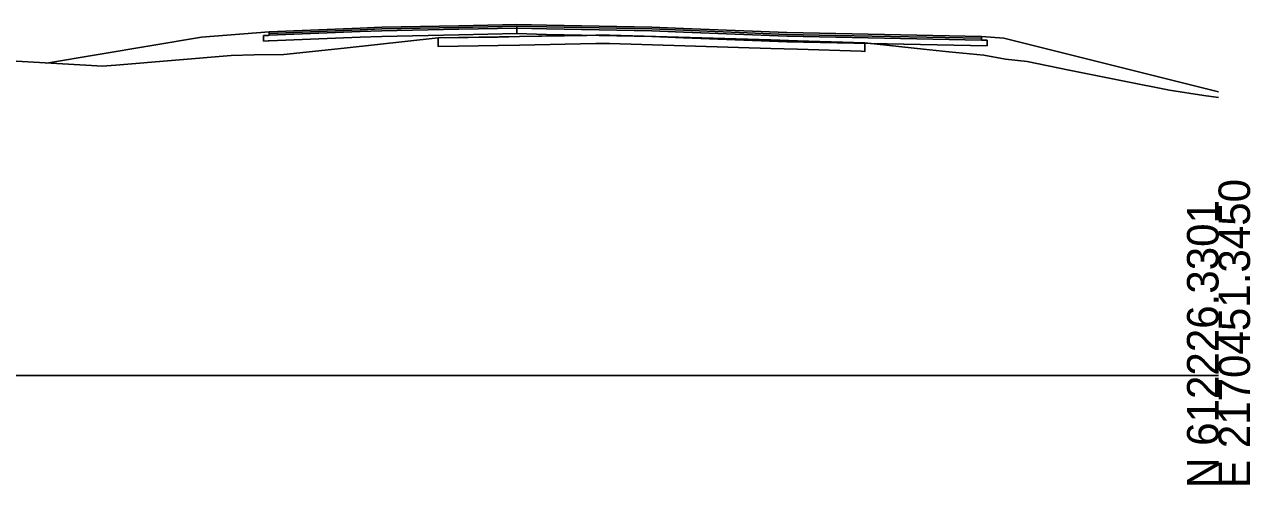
# Model space of a CAD drawing. Extents: x -26 to 1303, y -3010 to 12038.
# Drawn here: x 193.9 to 302.8, y 10990.3 to 11031.2 of the extents above; entities that cross this region are included whole.
import ezdxf

# ---------------------------------------------------------------- set-up
doc = ezdxf.new("R2010")
doc.units = 0
for name, color, linetype in [('RD_GPK_XS_Cell', 7, 'Continuous'), ('RD_XS_Base', 7, 'Continuous'), ('RD_XS_ExGround', 7, 'Continuous'), ('RD_XS_ExPaveRet', 7, 'Continuous'), ('RD_XS_Greenside', 7, 'Continuous'), ('RD_XS_Pave', 7, 'Continuous'), ('RD_XS_PaveOvlay_CP', 7, 'Continuous'), ('RD_XS_TieSlope', 7, 'Continuous')]:
    doc.layers.add(name, color=color, linetype=linetype)

msp = doc.modelspace()

# ---------------------------------------------------------------- linework, layer by layer
at = {"layer": 'RD_GPK_XS_Cell'}
msp.add_line((150, 11000), (300, 11000), dxfattribs=at)
at = {"layer": 'RD_XS_Base'}
for p, q in [((215.13, 11030.25), (215.54, 11030.26)), ((215.13, 11030.16), (215.13, 11030.25)), ((215.13, 11029.75), (215.13, 11030.16)), ((215.54, 11030.26), (215.63, 11030.27)), ((215.63, 11030.27), (223.73, 11030.59)), ((223.73, 11030.59), (225.63, 11030.67)), ((225.63, 11030.17), (223.73, 11030.09)), ((225.63, 11030.67), (232.5, 11030.8)), ((232.5, 11030.3), (225.63, 11030.17)), ((232.5, 11030.8), (237.63, 11030.91)), ((237.63, 11030.41), (232.5, 11030.3)), ((237.63, 11031.03), (237.63, 11031.07)), ((237.63, 11031.07), (237.63, 11030.92)), ((237.63, 11030.91), (237.63, 11031.03)), ((237.63, 11030.92), (237.63, 11030.41)), ((237.63, 11030.91), (237.63, 11030.91)), ((240.29, 11030.85), (237.63, 11030.91)), ((237.63, 11030.91), (237.63, 11030.91)), ((237.63, 11030.91), (237.63, 11030.8)), ((237.63, 11030.8), (237.63, 11030.41)), ((237.63, 11030.41), (240.29, 11030.35)), ((249.63, 11030.67), (240.29, 11030.85)), ((240.29, 11030.35), (249.63, 11030.17)), ((252.46, 11030.55), (249.63, 11030.67)), ((249.63, 11030.17), (252.46, 11030.05)), ((261.63, 11030.19), (252.46, 11030.55)), ((265.98, 11030.1), (261.63, 11030.19)), ((278.93, 11029.84), (265.98, 11030.1)), ((215.54, 11029.76), (215.13, 11029.75)), ((215.63, 11029.77), (215.54, 11029.76)), ((223.73, 11030.09), (215.63, 11029.77)), ((252.46, 11030.05), (261.63, 11029.69)), ((261.63, 11029.69), (266.11, 11029.6)), ((266.11, 11029.6), (279.43, 11029.33)), ((279.06, 11029.84), (278.93, 11029.84)), ((279.43, 11029.83), (279.06, 11029.84)), ((279.43, 11029.7), (279.43, 11029.83)), ((279.43, 11029.33), (279.43, 11029.7))]:
    msp.add_line(p, q, dxfattribs=at)
at = {"layer": 'RD_XS_ExGround'}
msp.add_lwpolyline([(183.88, 11028.51), (199.83, 11027.57), (200.78, 11027.51), (202.01, 11027.61), (212.24, 11028.47), (214.3, 11028.52), (216.92, 11028.56), (222.3, 11029.12), (230.64, 11030.03), (237.89, 11030.15), (245.89, 11030.29), (262.59, 11029.77), (268.58, 11029.58), (273.79, 11029.03), (276.02, 11028.79), (279.14, 11028.5), (281.06, 11028.15), (282.99, 11027.94), (286.72, 11027.15), (291.6, 11026.18), (295.65, 11025.37), (298.68, 11024.91), (300, 11024.73)], dxfattribs=at)
at = {"layer": 'RD_XS_ExPaveRet'}
for q in [(268.25, 11029.59), (268.58, 11029.58)]:
    msp.add_line((268.58, 11029.58), q, dxfattribs=at)
for points in [[(268.58, 11029.58), (268.58, 11029.58), (268.58, 11028.9), (268.58, 11028.83), (268.58, 11028.83), (268.58, 11028.83), (268.25, 11028.84), (262.59, 11029.02), (260.22, 11029.1), (245.89, 11029.54), (244.65, 11029.52), (237.89, 11029.4), (235.97, 11029.36), (230.64, 11029.28), (230.64, 11029.46), (230.64, 11030.03), (235.97, 11030.11), (237.89, 11030.15), (244.65, 11030.27), (245.89, 11030.29), (260.22, 11029.85), (262.59, 11029.77), (268.25, 11029.59), (268.58, 11029.58), (268.58, 11029.58)], [(260.22, 11029.85), (245.89, 11030.29), (244.65, 11030.27), (237.89, 11030.15), (235.97, 11030.11), (230.64, 11030.03)], [(230.64, 11030.03), (230.64, 11029.46), (230.64, 11029.28), (235.97, 11029.36), (237.89, 11029.4), (244.65, 11029.52), (245.89, 11029.54), (260.22, 11029.1), (262.59, 11029.02), (268.25, 11028.84), (268.58, 11028.83), (268.58, 11028.83), (268.58, 11028.9), (268.58, 11029.58)], [(268.25, 11029.59), (262.59, 11029.77), (260.22, 11029.85)]]:
    msp.add_lwpolyline(points, dxfattribs=at)
at = {"layer": 'RD_XS_Greenside'}
for p, q in [((209.63, 11030.1), (195.84, 11027.8)), ((280.93, 11030), (300, 11025.24))]:
    msp.add_line(p, q, dxfattribs=at)
at = {"layer": 'RD_XS_Pave'}
for p, q in [((237.63, 11031.23), (232.5, 11031.12)), ((240.29, 11031.17), (237.63, 11031.23)), ((223.73, 11030.91), (215.63, 11030.58)), ((223.73, 11030.75), (215.63, 11030.42)), ((215.63, 11030.42), (223.73, 11030.75)), ((215.63, 11030.27), (223.73, 11030.59)), ((215.63, 11030.58), (215.63, 11030.56)), ((215.63, 11030.56), (215.63, 11030.42)), ((215.63, 11030.42), (215.63, 11030.4)), ((215.63, 11030.4), (215.63, 11030.27)), ((225.63, 11030.98), (223.73, 11030.91)), ((225.63, 11030.83), (223.73, 11030.75)), ((223.73, 11030.75), (225.63, 11030.83)), ((223.73, 11030.59), (225.63, 11030.67)), ((232.5, 11031.12), (225.63, 11030.98)), ((232.5, 11030.96), (225.63, 11030.83)), ((225.63, 11030.83), (232.5, 11030.96)), ((225.63, 11030.67), (232.5, 11030.8)), ((237.63, 11031.07), (232.5, 11030.96)), ((232.5, 11030.96), (237.63, 11031.07)), ((232.5, 11030.8), (237.63, 11030.91)), ((237.63, 11031.03), (237.63, 11031.07)), ((237.63, 11031.07), (240.29, 11031.01)), ((240.29, 11031.01), (237.63, 11031.07)), ((237.63, 11031.07), (237.63, 11031.07)), ((237.63, 11031.07), (237.63, 11031.07)), ((237.63, 11031.07), (237.63, 11031.03)), ((237.63, 11030.91), (237.63, 11031.03)), ((237.63, 11031.03), (237.63, 11030.91)), ((237.63, 11030.91), (237.63, 11030.91)), ((237.63, 11030.91), (237.63, 11030.91)), ((237.63, 11030.91), (240.29, 11030.85)), ((249.63, 11030.99), (240.29, 11031.17)), ((240.29, 11031.01), (249.63, 11030.83)), ((249.63, 11030.83), (240.29, 11031.01)), ((240.29, 11030.85), (249.63, 11030.67)), ((252.46, 11030.87), (249.63, 11030.99)), ((249.63, 11030.83), (252.46, 11030.71)), ((252.46, 11030.71), (249.63, 11030.83)), ((249.63, 11030.67), (252.46, 11030.55)), ((261.63, 11030.51), (252.46, 11030.87)), ((252.46, 11030.71), (261.63, 11030.35)), ((261.63, 11030.35), (252.46, 11030.71)), ((252.46, 11030.55), (261.63, 11030.19)), ((265.98, 11030.42), (261.63, 11030.51)), ((261.63, 11030.35), (265.98, 11030.26)), ((265.98, 11030.26), (261.63, 11030.35)), ((261.63, 11030.19), (265.98, 11030.1)), ((278.93, 11030.16), (265.98, 11030.42)), ((265.98, 11030.26), (278.93, 11030)), ((278.93, 11030), (265.98, 11030.26)), ((265.98, 11030.1), (278.93, 11029.84)), ((278.93, 11030.12), (278.93, 11030.16)), ((278.93, 11030), (278.93, 11030.12)), ((278.93, 11029.96), (278.93, 11030)), ((278.93, 11029.84), (278.93, 11029.96))]:
    msp.add_line(p, q, dxfattribs=at)
at = {"layer": 'RD_XS_PaveOvlay_CP'}
for p, q in [((237.63, 11031.23), (232.5, 11031.12)), ((240.29, 11031.17), (237.63, 11031.23)), ((223.73, 11030.91), (215.63, 11030.58)), ((225.63, 11030.98), (223.73, 11030.91)), ((232.5, 11031.12), (225.63, 11030.98)), ((249.63, 11030.99), (240.29, 11031.17)), ((252.46, 11030.87), (249.63, 11030.99)), ((261.63, 11030.51), (252.46, 11030.87)), ((265.98, 11030.42), (261.63, 11030.51)), ((278.93, 11030.16), (265.98, 11030.42))]:
    msp.add_line(p, q, dxfattribs=at)
at = {"layer": 'RD_XS_TieSlope'}
for p, q in [((215.63, 11030.58), (209.63, 11030.1)), ((278.93, 11030.16), (280.93, 11030))]:
    msp.add_line(p, q, dxfattribs=at)

# ---------------------------------------------------------------- texts
at = {"layer": 'RD_GPK_XS_Cell'}
for s, p in [('E 2170451.3450', (302.8, 10990)), ('N 612226.3301', (300, 10990))]:
    msp.add_text(s, height=2.8, rotation=90, dxfattribs=at).set_placement(p)

doc.saveas('drawing.dxf')
